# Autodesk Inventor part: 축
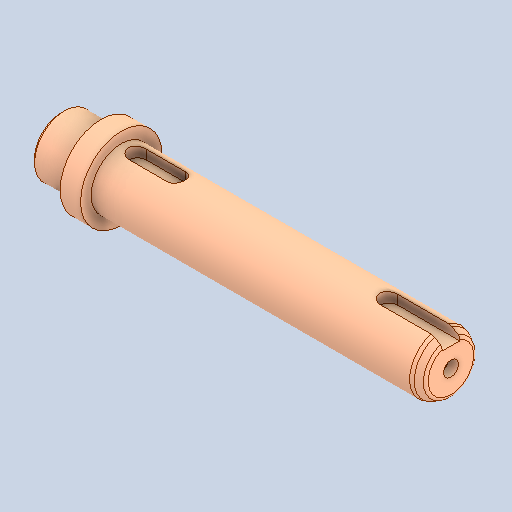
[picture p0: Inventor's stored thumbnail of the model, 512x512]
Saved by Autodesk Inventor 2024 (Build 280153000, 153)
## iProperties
Created: 2026-01
Part Number: 축
Material: 강철, 탄소
Document SubType Name: Modeling
Designer: 2-10
Density: 7.85 g/cm^3
Appearance: 기본값
Author: jhkim
Sending System: Autodesk Inventor 2026
Preprocessor: ST-DEVELOPER v20.1
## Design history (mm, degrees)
node "축1"
node "솔리드2"
node "솔리드1"
